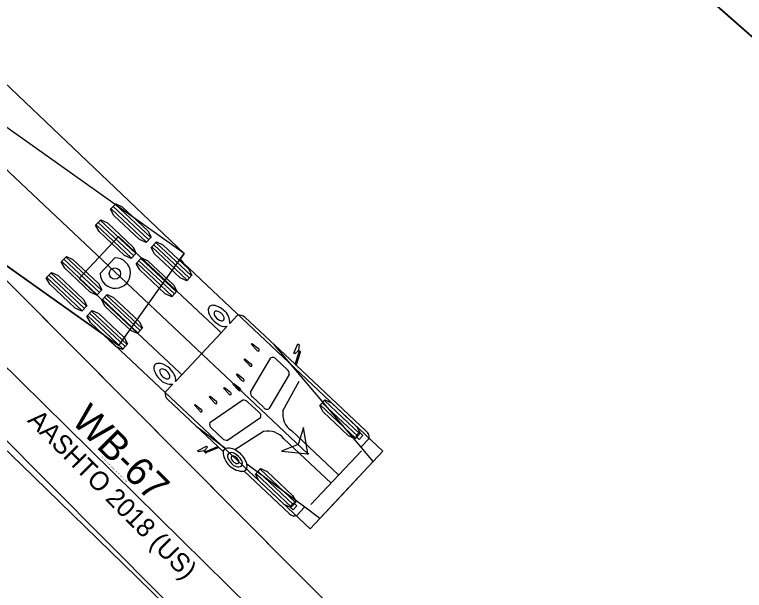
# Model space of a CAD drawing. Extents: x 973688 to 979179, y 703586 to 707602.
# Drawn here: x 976700.9 to 976755.9, y 705395.2 to 705438.6 of the extents above; entities that cross this region are included whole.
import ezdxf

# ---------------------------------------------------------------- set-up
doc = ezdxf.new("R2010")
doc.units = 0
for name, color, linetype in [('NB Right', 7, 'Continuous'), ('SB Left', 7, 'Continuous'), ('SB Right', 7, 'Continuous')]:
    doc.layers.add(name, color=color, linetype=linetype)

msp = doc.modelspace()

# ---------------------------------------------------------------- linework, layer by layer
at = {"layer": 'NB Right'}
for p, q in [((976648.857, 705475.314), (976722.992, 705405.513)), ((976711.154, 705421.786), (976708.479, 705424.294)), ((976710.84, 705421.452), (976708.166, 705423.96)), ((976710.997, 705421.619), (976708.322, 705424.127)), ((976709.711, 705420.248), (976707.037, 705422.756)), ((976709.868, 705420.415), (976707.194, 705422.924)), ((976710.025, 705420.582), (976707.35, 705423.091)), ((976713.904, 705418.578), (976711.229, 705421.087)), ((976714.06, 705418.746), (976711.386, 705421.254)), ((976714.217, 705418.913), (976711.543, 705421.421)), ((976707.123, 705417.488), (976704.449, 705419.997)), ((976707.28, 705417.656), (976704.605, 705420.164)), ((976707.437, 705417.823), (976704.762, 705420.331)), ((976708.444, 705420.258), (976707.338, 705419.08)), ((976712.932, 705417.542), (976710.257, 705420.05)), ((976713.088, 705417.709), (976710.414, 705420.218)), ((976712.775, 705417.375), (976710.1, 705419.883)), ((976705.994, 705416.285), (976703.32, 705418.793)), ((976706.151, 705416.452), (976703.477, 705418.96)), ((976706.308, 705416.619), (976703.633, 705419.128)), ((976710.343, 705414.782), (976707.669, 705417.291)), ((976710.5, 705414.95), (976707.826, 705417.458)), ((976710.187, 705414.615), (976707.512, 705417.124)), ((976709.215, 705413.579), (976706.54, 705416.087)), ((976709.371, 705413.746), (976706.697, 705416.254)), ((976709.058, 705413.412), (976706.383, 705415.92)), ((976713.487, 705411.459), (976716.45, 705414.618)), ((976718.745, 705413.742), (976718.806, 705413.807)), ((976719.119, 705413.337), (976718.745, 705413.742)), ((976718.806, 705413.807), (976719.234, 705413.46)), ((976720.384, 705413.786), (976726.983, 705406.007)), ((976722.285, 705413.288), (976722.288, 705413.315)), ((976718.661, 705410.157), (976720.199, 705412.739)), ((976722.265, 705413.268), (976722.285, 705413.288)), ((976718.193, 705412.59), (976718.255, 705412.655)), ((976718.586, 705412.169), (976718.193, 705412.59)), ((976718.255, 705412.655), (976718.701, 705412.291)), ((976720.605, 705412.631), (976721.43, 705411.857)), ((976722.025, 705412.247), (976722.098, 705412.178)), ((976717.604, 705411.473), (976717.666, 705411.539)), ((976717.978, 705411.069), (976717.604, 705411.473)), ((976717.666, 705411.539), (976718.093, 705411.191)), ((976721.587, 705411.483), (976720.048, 705408.901)), ((976717.346, 705410.747), (976717.407, 705410.812)), ((976717.72, 705410.342), (976717.346, 705410.747)), ((976717.407, 705410.812), (976717.835, 705410.465)), ((976721.118, 705408.737), (976722.344, 705410.97)), ((976716.638, 705410.443), (976716.699, 705410.508)), ((976717.012, 705410.038), (976716.638, 705410.443)), ((976716.699, 705410.508), (976717.127, 705410.161)), ((976715.561, 705409.783), (976715.623, 705409.849)), ((976715.935, 705409.379), (976715.561, 705409.783)), ((976718.08, 705409.538), (976715.602, 705407.837)), ((976715.623, 705409.849), (976716.05, 705409.501)), ((976719.643, 705409.01), (976718.818, 705409.783)), ((976726.907, 705407.006), (976724.238, 705409.52)), ((976714.447, 705409.159), (976714.508, 705409.225)), ((976714.821, 705408.754), (976714.447, 705409.159)), ((976714.508, 705409.225), (976714.936, 705408.877)), ((976719.288, 705408.632), (976718.464, 705409.405)), ((976726.593, 705406.672), (976723.923, 705409.186)), ((976726.75, 705406.839), (976724.08, 705409.353)), ((976716.944, 705406.533), (976719.423, 705408.234)), ((976714.569, 705407.586), (976716.822, 705405.911)), ((976715.736, 705407.439), (976716.561, 705406.666)), ((976725.319, 705403.903), (976721.751, 705407.249)), ((976719.655, 705407.177), (976717.494, 705405.803)), ((976726.605, 705406.825), (976726.887, 705407.126)), ((976726.864, 705406.581), (976726.605, 705406.825)), ((976727.146, 705406.882), (976726.864, 705406.581)), ((976726.887, 705407.126), (976727.146, 705406.882)), ((976724.748, 705403.294), (976721.18, 705406.641)), ((976715.188, 705405.721), (976715.161, 705405.716)), ((976715.206, 705405.742), (976715.188, 705405.721)), ((976716.21, 705406.047), (976716.283, 705405.978)), ((976723.229, 705401.676), (976727.035, 705405.733)), ((976718.4, 705404.737), (976722.755, 705401.499)), ((976721.746, 705401.507), (976719.076, 705404.021)), ((976721.903, 705401.674), (976719.234, 705404.187)), ((976722.06, 705401.841), (976719.391, 705404.354)), ((976721.914, 705401.824), (976721.632, 705401.523)), ((976722.174, 705401.581), (976721.914, 705401.824)), ((976721.632, 705401.523), (976721.892, 705401.28)), ((976721.892, 705401.28), (976722.174, 705401.581))]:
    msp.add_line(p, q, dxfattribs=at)
for points in [[(976665.615, 705444.321), (976665.603, 705444.303), (976665.66, 705444.262), (976670.28, 705440.98), (976708.753, 705413.651), (976711.214, 705417.116), (976713.675, 705420.58), (976675.202, 705447.909), (976670.582, 705451.191), (976670.524, 705451.232), (976670.512, 705451.214)], [(976690.15, 705442.899), (976698.005, 705435.473), (976713.675, 705420.58), (976713.375, 705420.158), (976713.595, 705419.885), (976728.644, 705405.697), (976723.173, 705399.859), (976707.617, 705414.455), (976673.07, 705438.998)], [(976713.018, 705410.958), (976713.487, 705411.458), (976713.314, 705411.622), (976705.756, 705418.71), (976707.237, 705420.29), (976708.718, 705421.869), (976716.276, 705414.78), (976716.45, 705414.618), (976716.919, 705415.118)], [(976717.112, 705415.324), (976717.69, 705415.94)], [(976718.25, 705415.788), (976722.025, 705412.247), (976722.342, 705413.177), (976722.342, 705413.178), (976722.324, 705413.211), (976722.324, 705413.212), (976722.323, 705413.213), (976722.265, 705413.268), (976722.264, 705413.268), (976722.014, 705413.024), (976721.939, 705413.095), (976722.244, 705413.795), (976722.245, 705413.796), (976722.332, 705413.715), (976722.332, 705413.712), (976722.288, 705413.318), (976722.289, 705413.315), (976722.351, 705413.255)], [(976722.419, 705413.131), (976722.101, 705412.188), (976722.104, 705412.173), (976727.397, 705407.209)], [(976712.247, 705410.136), (976712.825, 705410.753)], [(976715.225, 705405.657), (976715.161, 705405.715), (976715.158, 705405.716), (976714.768, 705405.647), (976714.765, 705405.647), (976714.678, 705405.728), (976714.679, 705405.729), (976715.358, 705406.078), (976715.434, 705406.008), (976715.207, 705405.743), (976715.207, 705405.742), (976715.266, 705405.687), (976715.266, 705405.687), (976715.267, 705405.687), (976715.302, 705405.67), (976715.302, 705405.67), (976716.21, 705406.047), (976712.435, 705409.588)], [(976722.992, 705405.513), (976722.671, 705407.487), (976722.264, 705406.199), (976721.002, 705405.715), (976722.992, 705405.513)], [(976727.575, 705406.638), (976726.988, 705406.013), (976726.984, 705406.005), (976727.911, 705404.912), (976727.868, 705404.865), (976725.909, 705402.777), (976723.951, 705400.688), (976723.907, 705400.643), (976722.757, 705401.498), (976722.749, 705401.493), (976722.163, 705400.868)], [(976716.6, 705405.681), (976716.289, 705405.973), (976716.274, 705405.974), (976715.353, 705405.597)], [(976721.582, 705401.009), (976718.194, 705404.186)]]:
    msp.add_lwpolyline(points, dxfattribs=at)
for points in [[(976711.192, 705421.827), (976710.801, 705421.41), (976710.309, 705421.636), (976708.383, 705423.442), (976708.127, 705423.918), (976708.518, 705424.336), (976709.01, 705424.11), (976710.936, 705422.304)], [(976710.064, 705420.624), (976709.672, 705420.207), (976709.18, 705420.432), (976707.254, 705422.238), (976706.998, 705422.715), (976707.389, 705423.132), (976707.882, 705422.907), (976709.807, 705421.101)], [(976714.256, 705418.954), (976713.865, 705418.537), (976713.372, 705418.762), (976711.447, 705420.568), (976711.19, 705421.045), (976711.581, 705421.462), (976712.074, 705421.237), (976713.999, 705419.431)], [(976707.476, 705417.864), (976707.084, 705417.447), (976706.592, 705417.672), (976704.666, 705419.478), (976704.41, 705419.955), (976704.801, 705420.373), (976705.293, 705420.147), (976707.219, 705418.341)], [(976713.127, 705417.751), (976712.736, 705417.333), (976712.244, 705417.559), (976710.318, 705419.365), (976710.061, 705419.842), (976710.453, 705420.259), (976710.945, 705420.033), (976712.871, 705418.228)], [(976706.347, 705416.661), (976705.956, 705416.244), (976705.463, 705416.469), (976703.538, 705418.275), (976703.281, 705418.752), (976703.672, 705419.169), (976704.165, 705418.944), (976706.09, 705417.138)], [(976710.539, 705414.991), (976710.148, 705414.574), (976709.655, 705414.799), (976707.73, 705416.605), (976707.473, 705417.082), (976707.865, 705417.499), (976708.357, 705417.274), (976710.283, 705415.468)], [(976709.41, 705413.788), (976709.019, 705413.37), (976708.527, 705413.596), (976706.601, 705415.402), (976706.345, 705415.879), (976706.736, 705416.296), (976707.228, 705416.07), (976709.154, 705414.264)], [(976726.946, 705407.047), (976726.554, 705406.631), (976726.062, 705406.857), (976724.14, 705408.667), (976723.884, 705409.145), (976724.277, 705409.561), (976724.768, 705409.335), (976726.691, 705407.525)], [(976722.992, 705405.513), (976722.671, 705407.487), (976722.264, 705406.199), (976721.002, 705405.715)], [(976722.099, 705401.882), (976721.707, 705401.466), (976721.215, 705401.692), (976719.293, 705403.502), (976719.038, 705403.979), (976719.43, 705404.396), (976719.922, 705404.169), (976721.844, 705402.359)]]:
    msp.add_lwpolyline(points, close=True, dxfattribs=at)
for centre, radius in [((976708.452, 705419.078), 0.424), ((976722.992, 705405.513), 0.0417)]:
    msp.add_circle(centre, radius, dxfattribs=at)
for centre, radius, start, end in [((976708.48, 705419.116), 1.143, 181.8363, 91.8363), ((976715.826, 705416.344), 0.346, 80.229, 177.242), ((976715.684, 705415.283), 1.416, 44.7644, 81.8323), ((976716.615, 705416.412), 1.136, 182.6002, 224.121), ((976716.283, 705416.08), 0.362, 171.1328, 220.1738), ((976716.091, 705416.09), 0.172, 77.1379, 164.2885), ((976716.013, 705415.603), 0.664, 41.7401, 79.9618), ((976716.166, 705415.651), 0.522, 1.8416, 49.0057), ((976715.978, 705415.394), 1.136, 356.4662, 51.2575), ((976717.112, 705416.748), 1.73, 220.6629, 245.4614), ((976716.627, 705416.235), 0.732, 212.0101, 258.2445), ((976716.52, 705415.681), 0.169, 255.2706, 355.3893), ((976717.826, 705415.336), 0.619, 46.8342, 102.6759), ((976716.729, 705415.822), 0.729, 242.6447, 285.1587), ((976719.272, 705413.439), 0.184, 213.7894, 285.6814), ((976719.174, 705413.315), 0.157, 340.3822, 67.4919), ((976720.335, 705412.436), 0.332, 35.7577, 114.1797), ((976722.34, 705413.148), 0.108, 37.6774, 83.8599), ((976722.39, 705413.175), 0.0522, 303.099, 47.9537), ((976711.725, 705411.971), 0.346, 96.4305, 193.4436), ((976711.707, 705411.179), 1.136, 49.5515, 91.0723), ((976718.622, 705412.163), 0.157, 340.3822, 67.4919), ((976712.774, 705412.181), 1.416, 191.8402, 228.9081), ((976711.995, 705411.723), 0.172, 109.3841, 196.5347), ((976712.476, 705411.831), 0.664, 193.7107, 231.9324), ((976712.017, 705411.532), 0.362, 53.4987, 102.5397), ((976711.885, 705411.179), 0.732, 15.428, 61.6624), ((976711.403, 705410.661), 1.73, 28.2111, 53.0096), ((976718.72, 705412.288), 0.184, 213.7894, 285.6814), ((976721.204, 705411.543), 0.387, 351.1691, 54.4011), ((976712.682, 705411.88), 1.136, 222.415, 277.2063), ((976712.438, 705411.676), 0.522, 224.6668, 271.8309), ((976712.43, 705411.32), 0.169, 278.2832, 18.4019), ((976712.303, 705411.103), 0.729, 348.5138, 31.0278), ((976718.033, 705411.046), 0.157, 340.3822, 67.4919), ((976718.131, 705411.171), 0.184, 213.7894, 285.6814), ((976712.858, 705410.039), 0.619, 170.9966, 226.8383), ((976717.153, 705410.107), 0.157, 206.1806, 293.2903), ((976717.034, 705410.001), 0.184, 347.9911, 59.8831), ((976717.861, 705410.411), 0.157, 206.1806, 293.2903), ((976717.775, 705410.32), 0.157, 340.3822, 67.4919), ((976719.043, 705410.098), 0.387, 171.1716, 234.3986), ((976715.958, 705409.342), 0.184, 347.9911, 59.8831), ((976718.164, 705409.16), 0.387, 39.2739, 102.501), ((976716.076, 705409.448), 0.157, 206.1806, 293.2903), ((976719.9, 705409.157), 0.296, 209.8198, 300.1175), ((976714.962, 705408.824), 0.157, 206.1806, 293.2903), ((976714.844, 705408.718), 0.184, 347.9911, 59.8831), ((976719.158, 705408.366), 0.296, 333.555, 63.8527), ((976722.615, 705408.495), 1.517, 170.8288, 235.2562), ((976715.913, 705407.721), 0.332, 159.4928, 237.9149), ((976719.992, 705405.698), 1.517, 38.4163, 102.8437), ((976727.12, 705406.81), 0.486, 339.2992, 55.2503), ((976716.86, 705406.911), 0.387, 219.2714, 282.5034), ((976715.331, 705405.675), 0.108, 189.8126, 235.9951), ((976715.307, 705405.623), 0.0522, 225.7189, 330.5735), ((976716.936, 705405.584), 0.347, 109.1635, 163.974), ((976718.132, 705405.715), 1.53, 181.329, 272.338), ((976717.006, 705404.79), 1.136, 45.5408, 99.3434), ((976717.237, 705405.151), 0.44, 58.6305, 122.4433), ((976716.769, 705404.246), 1.704, 16.7569, 52.665), ((976717.253, 705405.33), 0.317, 142.6864, 204.2788), ((976717.934, 705405.547), 1.03, 199.6599, 228.0464), ((976717.382, 705405.196), 0.17, 144.5053, 198.5697), ((976717.776, 705405.34), 0.589, 199.5918, 242.5745), ((976717.373, 705405.067), 0.263, 45.7712, 119.6731), ((976716.942, 705404.459), 1.189, 27.9675, 63.8568), ((976717.239, 705404.775), 0.575, 19.9114, 56.4817), ((976717.749, 705405.166), 0.634, 217.4201, 293.4218), ((976717.635, 705404.997), 0.223, 234.0712, 303.6736), ((976717.635, 705404.909), 0.158, 321.8075, 23.3202), ((976717.702, 705404.795), 0.366, 324.8886, 37.3696), ((976718.004, 705404.582), 0.425, 294.8992, 21.4355), ((976721.963, 705401.311), 0.486, 218.4222, 294.3733)]:
    msp.add_arc(centre, radius, start, end, dxfattribs=at)
for centre, major_axis, start_param, end_param in [((976722.386, 705413.193), (0.0571, -0.0535), 2.615166, 3.884468), ((976722.386, 705413.193), (-0.0571, 0.0535), 1.301202, 2.571945), ((976715.289, 705405.626), (0.0571, -0.0535), 2.398717, 3.668019), ((976715.289, 705405.626), (0.0571, -0.0535), 0.569648, 1.840391)]:
    msp.add_ellipse(centre, major_axis=major_axis, ratio=0.544872, start_param=start_param, end_param=end_param, dxfattribs=at)
at = {"layer": 'SB Left'}
msp.add_line((976679.446, 705432.472), (976739.213, 705373.726), dxfattribs=at)
for points in [[(976677.487, 705441.611), (976684.948, 705433.998), (976692.419, 705426.441), (976730.42, 705388.251), (976730.478, 705387.938), (976744.87, 705373.781), (976739.268, 705368.069), (976724.601, 705382.457), (976724.395, 705382.255), (976709.085, 705397.211), (976701.404, 705404.671), (976693.707, 705412.092), (976689.931, 705415.701), (976686.142, 705419.295), (976682.28, 705422.921), (976678.351, 705426.563), (976674.387, 705430.175), (976670.378, 705433.749), (976668.353, 705435.517), (976666.311, 705437.272), (976664.25, 705439.01)], [(976687.074, 705419.788), (976687.059, 705419.773), (976687.109, 705419.723), (976691.106, 705415.705), (976724.395, 705382.255), (976727.407, 705385.253), (976730.42, 705388.251), (976697.131, 705421.701), (976693.133, 705425.717), (976693.083, 705425.768), (976693.068, 705425.752)]]:
    msp.add_lwpolyline(points, dxfattribs=at)
at = {"layer": 'SB Right'}
for points in [[(976788.218, 705420.357), (976788.232, 705420.373), (976788.179, 705420.42), (976783.92, 705424.158), (976748.449, 705455.284), (976745.645, 705452.09), (976742.842, 705448.895), (976778.314, 705417.769), (976782.574, 705414.032), (976782.627, 705413.985), (976782.641, 705414.002)], [(976782.674, 705413.943), (976751.717, 705441.107)]]:
    msp.add_lwpolyline(points, dxfattribs=at)

# ---------------------------------------------------------------- texts
at = {"layer": 'SB Left'}
for s, height, p in [('WB-67', 2.125, (976705.087, 705407.922)), ('AASHTO 2018 (US)', 1.41667, (976701.796, 705407.966)), ('(c) 2020 Transoft Solutions, Inc. All rights reserved.', 0.085, (976707.456, 705405.24))]:
    msp.add_text(s, height=height, rotation=314.8615, dxfattribs=at).set_placement(p)

doc.saveas('drawing.dxf')
